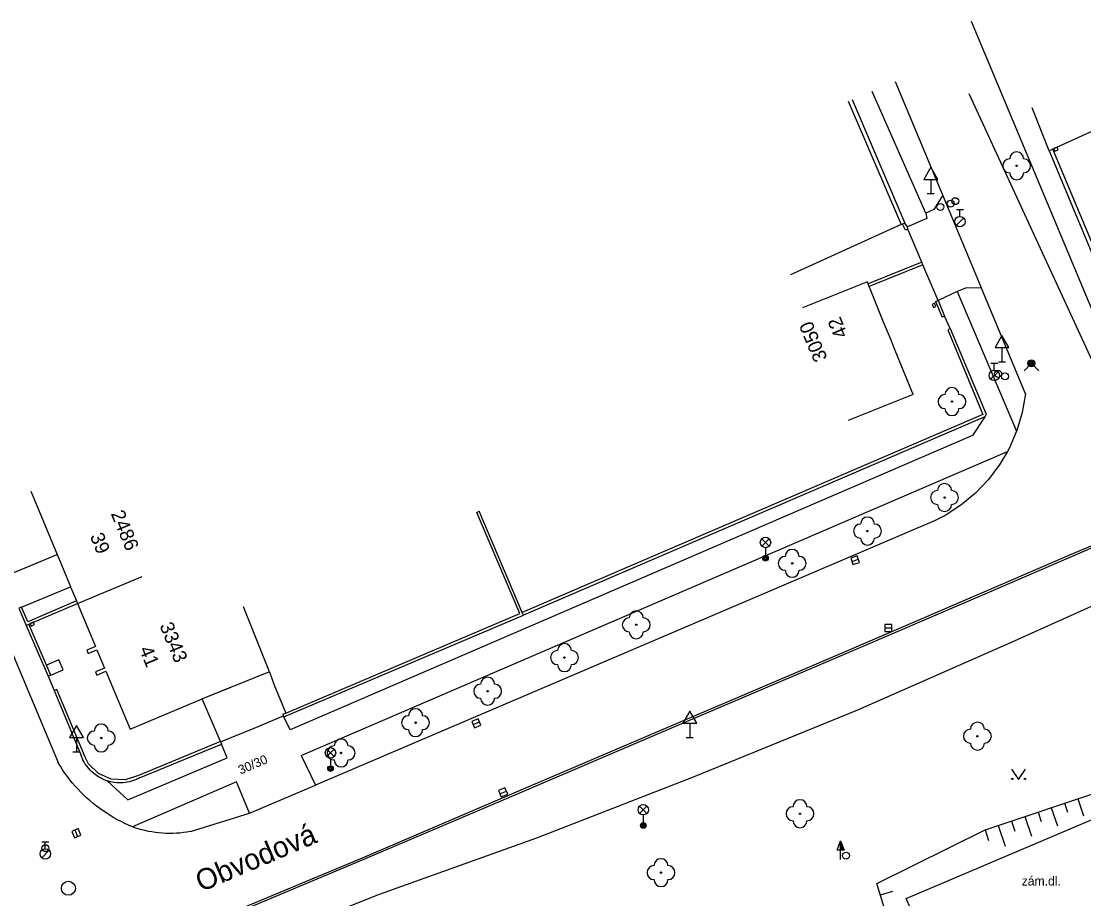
# Model space of a CAD drawing. Extents: x -539694 to -539148, y -1156467 to -1155920.
# Drawn here: x -539556.6 to -539480.5, y -1156053.8 to -1155991 of the extents above; entities that cross this region are included whole.
import ezdxf

# ---------------------------------------------------------------- set-up
doc = ezdxf.new("R2010")
doc.units = 0
for name, color, linetype in [('Vrstva 10', 7, 'Continuous'), ('Vrstva 11', 7, 'Continuous'), ('Vrstva 14', 7, 'Continuous'), ('Vrstva 15', 7, 'Continuous'), ('Vrstva 22', 7, 'Continuous'), ('Vrstva 23', 7, 'Continuous'), ('Vrstva 24', 7, 'Continuous'), ('Vrstva 27', 7, 'Continuous'), ('Vrstva 28', 7, 'Continuous'), ('Vrstva 31', 7, 'Continuous'), ('Vrstva 33', 7, 'Continuous'), ('Vrstva 34', 7, 'Continuous'), ('Vrstva 36', 7, 'Continuous'), ('Vrstva 40', 7, 'Continuous'), ('Vrstva 46', 7, 'Continuous'), ('Vrstva 47', 7, 'Continuous'), ('Vrstva 49', 7, 'Continuous'), ('Vrstva 5', 7, 'Continuous'), ('Vrstva 6', 7, 'Continuous'), ('Vrstva 7', 7, 'Continuous'), ('Vrstva 8', 7, 'Continuous')]:
    doc.layers.add(name, color=color, linetype=linetype)

msp = doc.modelspace()

# ---------------------------------------------------------------- linework, layer by layer
at = {"layer": 'Vrstva 10'}
for p, q in [((-539490.641, -1156003.461), (-539494.017, -1155995.353)), ((-539488.78, -1155996.19), (-539479.82, -1156015.6)), ((-539488.011, -1156009.777), (-539490.641, -1156003.461)), ((-539487.865, -1156010.127), (-539488.011, -1156009.777)), ((-539484.718, -1156017.686), (-539487.865, -1156010.127)), ((-539491.222, -1156026.789), (-539535.54, -1156045.71)), ((-539558.31, -1156033.77), (-539553.97, -1156044.1)), ((-539540.26, -1156047.72), (-539535.54, -1156045.71)), ((-539544.5, -1156049.04), (-539540.26, -1156047.72))]:
    msp.add_line(p, q, dxfattribs=at)
for points in [[(-539484.718, -1156017.686), (-539484.948, -1156019.021), (-539485.334, -1156020.32), (-539485.352, -1156020.371), (-539485.87, -1156021.564), (-539486.008, -1156021.831), (-539486.548, -1156022.737), (-539487.361, -1156023.821), (-539488.295, -1156024.803), (-539489.338, -1156025.667)], [(-539489.338, -1156025.667), (-539490.476, -1156026.402), (-539491.222, -1156026.789)], [(-539548.65, -1156048.7), (-539548.924, -1156048.583), (-539549.194, -1156048.459), (-539549.462, -1156048.327), (-539549.725, -1156048.189), (-539549.985, -1156048.043), (-539550.24, -1156047.891), (-539550.492, -1156047.732), (-539550.739, -1156047.565), (-539550.982, -1156047.393), (-539551.22, -1156047.214), (-539551.453, -1156047.028), (-539551.68, -1156046.837), (-539551.903, -1156046.639), (-539552.12, -1156046.436), (-539552.332, -1156046.226), (-539552.538, -1156046.011), (-539552.738, -1156045.791), (-539552.933, -1156045.565), (-539553.121, -1156045.335), (-539553.302, -1156045.099), (-539553.478, -1156044.858), (-539553.647, -1156044.613), (-539553.809, -1156044.363), (-539553.964, -1156044.109), (-539553.97, -1156044.1)], [(-539544.5, -1156049.04), (-539544.748, -1156049.082), (-539544.997, -1156049.117), (-539545.246, -1156049.143), (-539545.497, -1156049.162), (-539545.748, -1156049.172), (-539545.999, -1156049.175), (-539546.25, -1156049.169), (-539546.501, -1156049.156), (-539546.752, -1156049.135), (-539547.001, -1156049.105), (-539547.25, -1156049.068), (-539547.497, -1156049.023), (-539547.742, -1156048.97), (-539547.986, -1156048.909), (-539548.228, -1156048.84), (-539548.467, -1156048.764), (-539548.65, -1156048.7)]]:
    msp.add_lwpolyline(points, dxfattribs=at)
at = {"layer": 'Vrstva 11'}
for p, q in [((-539488.6, -1155991.01), (-539478.29, -1156015.69)), ((-539491.86, -1156004.76), (-539495.69, -1155996.05)), ((-539490.641, -1156003.461), (-539491.28, -1156004.48)), ((-539491.28, -1156004.48), (-539491.86, -1156004.76)), ((-539491.77, -1156005.13), (-539493.17, -1156005.74)), ((-539491.86, -1156004.76), (-539491.77, -1156005.13)), ((-539489.62, -1156010.36), (-539490.98, -1156011.01)), ((-539488.94, -1156010.09), (-539489.62, -1156010.36)), ((-539489.62, -1156010.36), (-539485.352, -1156020.371)), ((-539487.865, -1156010.127), (-539488.94, -1156010.09)), ((-539487.64, -1156019.33), (-539488.52, -1156020.67)), ((-539488.52, -1156020.67), (-539537.35, -1156041.76)), ((-539536.56, -1156043.59), (-539486.008, -1156021.831)), ((-539481.48, -1156029.36), (-539478.17, -1156027.94)), ((-539557.485, -1156030.633), (-539554.04, -1156029.193)), ((-539487.67, -1156031.88), (-539481.54, -1156029.23)), ((-539487.61, -1156032.01), (-539481.48, -1156029.36)), ((-539556.586, -1156032.972), (-539553.074, -1156031.505)), ((-539498.23, -1156036.41), (-539487.67, -1156031.88)), ((-539498.17, -1156036.54), (-539487.61, -1156032.01)), ((-539509.37, -1156041.16), (-539498.23, -1156036.41)), ((-539509.31, -1156041.29), (-539498.17, -1156036.54)), ((-539542.356, -1156042.585), (-539543.651, -1156039.523)), ((-539537.35, -1156041.76), (-539537.8, -1156040.82)), ((-539520.81, -1156046.06), (-539509.37, -1156041.16)), ((-539520.75, -1156046.19), (-539509.31, -1156041.29)), ((-539541.87, -1156043.75), (-539542.28, -1156042.77)), ((-539548.97, -1156046.76), (-539541.87, -1156043.75)), ((-539536.56, -1156043.59), (-539535.54, -1156045.71)), ((-539550.45, -1156045.41), (-539548.97, -1156046.76)), ((-539541.2, -1156045.47), (-539548.65, -1156048.7)), ((-539540.26, -1156047.72), (-539541.2, -1156045.47)), ((-539493.25, -1156053.83), (-539473.93, -1156045.61)), ((-539532.19, -1156050.92), (-539520.81, -1156046.06)), ((-539532.14, -1156051.05), (-539520.75, -1156046.19)), ((-539541.52, -1156054.81), (-539532.19, -1156050.92)), ((-539541.55, -1156055), (-539532.14, -1156051.05))]:
    msp.add_line(p, q, dxfattribs=at)
for points in [[(-539481.54, -1156029.23), (-539478.25, -1156027.84), (-539476.58, -1156027.09)], [(-539554.496, -1156037.84), (-539553.607, -1156037.458), (-539553.92, -1156036.73), (-539554.809, -1156037.112)], [(-539493.4, -1156059.73), (-539492.62, -1156058.93), (-539492.11, -1156057.52), (-539492.33, -1156055.98), (-539493.25, -1156053.83)]]:
    msp.add_lwpolyline(points, dxfattribs=at)
at = {"layer": 'Vrstva 14'}
for p, q in [((-539487.61, -1156048.92), (-539473.92, -1156044.33)), ((-539495.35, -1156052.75), (-539487.61, -1156048.92)), ((-539493.93, -1156057.4), (-539495.35, -1156052.75))]:
    msp.add_line(p, q, dxfattribs=at)
at = {"layer": 'Vrstva 15'}
for p, q in [((-539481.921, -1156047.013), (-539481.71, -1156047.644)), ((-539480.973, -1156046.695), (-539480.564, -1156047.914)), ((-539484.766, -1156047.966), (-539484.299, -1156049.359)), ((-539483.817, -1156047.648), (-539483.591, -1156048.323)), ((-539482.869, -1156047.331), (-539482.431, -1156048.637)), ((-539486.662, -1156048.602), (-539486.166, -1156050.081)), ((-539485.714, -1156048.284), (-539485.473, -1156049.002)), ((-539487.61, -1156048.92), (-539487.355, -1156049.681)), ((-539495.098, -1156053.574), (-539494.212, -1156053.304))]:
    msp.add_line(p, q, dxfattribs=at)
at = {"layer": 'Vrstva 22'}
for centre in [(-539485.35, -1156001.36), (-539489.98, -1156018.25), (-539490.51, -1156025.12), (-539496.03, -1156027.52), (-539501.42, -1156029.83), (-539512.58, -1156034.23), (-539517.72, -1156036.58), (-539523.22, -1156038.99), (-539528.38, -1156041.24), (-539550.88, -1156042.34), (-539488.16, -1156042.21), (-539533.71, -1156043.41), (-539500.86, -1156047.76), (-539510.81, -1156051.98)]:
    msp.add_circle(centre, 0.05, dxfattribs=at)
for centre, start, end in [((-539485.35, -1156000.86), 0, 180), ((-539485.85, -1156001.36), 90, 270), ((-539484.85, -1156001.36), 270, 90), ((-539485.35, -1156001.86), 180, 0), ((-539489.98, -1156017.75), 0, 180), ((-539490.48, -1156018.25), 90, 270), ((-539489.48, -1156018.25), 270, 90), ((-539489.98, -1156018.75), 180, 0), ((-539490.51, -1156024.62), 0, 180), ((-539491.01, -1156025.12), 90, 270), ((-539490.01, -1156025.12), 270, 90), ((-539490.51, -1156025.62), 180, 0), ((-539496.03, -1156027.02), 0, 180), ((-539496.53, -1156027.52), 90, 270), ((-539495.53, -1156027.52), 270, 90), ((-539496.03, -1156028.02), 180, 0), ((-539501.42, -1156029.33), 0, 180), ((-539501.92, -1156029.83), 90, 270), ((-539500.92, -1156029.83), 270, 90), ((-539501.42, -1156030.33), 180, 0), ((-539512.58, -1156033.73), 0, 180), ((-539513.08, -1156034.23), 90, 270), ((-539512.08, -1156034.23), 270, 90), ((-539512.58, -1156034.73), 180, 0), ((-539517.72, -1156036.08), 0, 180), ((-539518.22, -1156036.58), 90, 270), ((-539517.22, -1156036.58), 270, 90), ((-539517.72, -1156037.08), 180, 0), ((-539523.22, -1156038.49), 0, 180), ((-539523.72, -1156038.99), 90, 270), ((-539522.72, -1156038.99), 270, 90), ((-539523.22, -1156039.49), 180, 0), ((-539528.38, -1156040.74), 0, 180), ((-539528.88, -1156041.24), 90, 270), ((-539527.88, -1156041.24), 270, 90), ((-539551.38, -1156042.34), 90, 270), ((-539550.88, -1156041.84), 0, 180), ((-539550.38, -1156042.34), 270, 90), ((-539528.38, -1156041.74), 180, 0), ((-539488.66, -1156042.21), 90, 270), ((-539488.16, -1156041.71), 0, 180), ((-539487.66, -1156042.21), 270, 90), ((-539533.71, -1156042.91), 0, 180), ((-539550.88, -1156042.84), 180, 0), ((-539534.21, -1156043.41), 90, 270), ((-539533.21, -1156043.41), 270, 90), ((-539488.16, -1156042.71), 180, 0), ((-539533.71, -1156043.91), 180, 0), ((-539500.86, -1156047.26), 0, 180), ((-539501.36, -1156047.76), 90, 270), ((-539500.36, -1156047.76), 270, 90), ((-539500.86, -1156048.26), 180, 0), ((-539510.81, -1156051.48), 0, 180), ((-539511.31, -1156051.98), 90, 270), ((-539510.31, -1156051.98), 270, 90), ((-539510.81, -1156052.48), 180, 0)]:
    msp.add_arc(centre, 0.5, start, end, dxfattribs=at)
at = {"layer": 'Vrstva 23'}
for p, q in [((-539485.73, -1156035.47), (-539476.98, -1156031.53)), ((-539496.72, -1156040.33), (-539485.73, -1156035.47)), ((-539508.48, -1156045.13), (-539496.72, -1156040.33)), ((-539519.7, -1156049.48), (-539508.48, -1156045.13)), ((-539530.96, -1156053.51), (-539519.7, -1156049.48)), ((-539541.12, -1156057.56), (-539530.96, -1156053.51))]:
    msp.add_line(p, q, dxfattribs=at)
at = {"layer": 'Vrstva 24'}
for p, q in [((-539482.457, -1156000.035), (-539482.689, -1156000.128)), ((-539482.383, -1156000.221), (-539482.457, -1156000.035)), ((-539482.689, -1156000.128), (-539482.615, -1156000.314)), ((-539482.615, -1156000.314), (-539482.383, -1156000.221)), ((-539491.223, -1156011.21), (-539491.408, -1156011.285)), ((-539491.408, -1156011.285), (-539491.314, -1156011.517)), ((-539491.314, -1156011.517), (-539491.129, -1156011.442)), ((-539491.129, -1156011.442), (-539491.223, -1156011.21)), ((-539555.749, -1156034.038), (-539555.979, -1156034.135)), ((-539555.979, -1156034.135), (-539555.901, -1156034.32)), ((-539555.901, -1156034.32), (-539555.671, -1156034.222)), ((-539555.671, -1156034.222), (-539555.749, -1156034.038))]:
    msp.add_line(p, q, dxfattribs=at)
at = {"layer": 'Vrstva 27'}
for p, q in [((-539497.148, -1156029.689), (-539496.676, -1156029.525)), ((-539494.79, -1156034.46), (-539494.29, -1156034.46)), ((-539524.259, -1156041.381), (-539523.799, -1156041.187)), ((-539522.342, -1156046.328), (-539521.882, -1156046.134)), ((-539552.764, -1156048.925), (-539552.57, -1156049.385))]:
    msp.add_line(p, q, dxfattribs=at)
for points in [[(-539497.067, -1156029.925), (-539496.594, -1156029.762), (-539496.757, -1156029.289), (-539497.23, -1156029.452)], [(-539494.79, -1156034.71), (-539494.29, -1156034.71), (-539494.29, -1156034.21), (-539494.79, -1156034.21)], [(-539524.162, -1156041.611), (-539523.702, -1156041.417), (-539523.896, -1156040.957), (-539524.356, -1156041.151)], [(-539522.245, -1156046.558), (-539521.785, -1156046.364), (-539521.979, -1156045.904), (-539522.439, -1156046.098)], [(-539552.995, -1156049.022), (-539552.8, -1156049.483), (-539552.339, -1156049.288), (-539552.534, -1156048.827)]]:
    msp.add_lwpolyline(points, close=True, dxfattribs=at)
msp.add_circle((-539553.235, -1156053.1), 0.5, dxfattribs=at)
at = {"layer": 'Vrstva 28'}
for p, q in [((-539489.664, -1156004.482), (-539489.164, -1156004.482)), ((-539489.414, -1156004.982), (-539489.414, -1156004.482)), ((-539489.672, -1156005.629), (-539489.142, -1156005.099)), ((-539487.204, -1156015.498), (-539486.704, -1156015.498)), ((-539486.954, -1156015.998), (-539486.954, -1156015.498)), ((-539487.212, -1156016.645), (-539486.682, -1156016.115)), ((-539555.136, -1156049.764), (-539554.636, -1156049.764)), ((-539554.886, -1156050.264), (-539554.886, -1156049.764)), ((-539498.2, -1156050.378), (-539497.95, -1156049.704)), ((-539555.144, -1156050.911), (-539554.614, -1156050.381)), ((-539497.95, -1156050.378), (-539498.2, -1156050.378)), ((-539497.95, -1156051.03), (-539497.95, -1156050.38))]:
    msp.add_line(p, q, dxfattribs=at)
for points in [[(-539497.7, -1156050.38), (-539497.95, -1156050.38), (-539497.95, -1156049.704), (-539497.7, -1156050.38)], [(-539497.756, -1156050.339), (-539497.911, -1156050.339), (-539497.909, -1156049.927)], [(-539497.815, -1156050.3), (-539497.871, -1156050.3), (-539497.871, -1156050.15)]]:
    msp.add_lwpolyline(points, close=True, dxfattribs=at)
for centre, radius in [((-539490.077, -1156004.068), 0.25), ((-539489.748, -1156003.895), 0.25), ((-539490.81, -1156004.31), 0.25), ((-539489.414, -1156005.357), 0.375), ((-539486.954, -1156016.373), 0.375), ((-539486.676, -1156016.261), 0.25), ((-539486.18, -1156016.44), 0.25), ((-539554.886, -1156050.639), 0.375), ((-539554.879, -1156050.227), 0.25), ((-539497.56, -1156050.76), 0.25)]:
    msp.add_circle(centre, radius, dxfattribs=at)
at = {"layer": 'Vrstva 31'}
msp.add_lwpolyline([(-539484.824, -1156016.037), (-539484.294, -1156015.507), (-539483.764, -1156016.037)], dxfattribs=at)
for radius in [0.25, 0.18, 0.11]:
    msp.add_circle((-539484.294, -1156015.507), radius, dxfattribs=at)
at = {"layer": 'Vrstva 33'}
for p, q in [((-539503.595, -1156028.6), (-539503.065, -1156028.07)), ((-539503.595, -1156028.07), (-539503.065, -1156028.6)), ((-539503.33, -1156028.71), (-539503.33, -1156029.46)), ((-539534.735, -1156043.67), (-539534.205, -1156043.14)), ((-539534.735, -1156043.14), (-539534.205, -1156043.67)), ((-539534.47, -1156043.78), (-539534.47, -1156044.53)), ((-539512.344, -1156047.741), (-539511.816, -1156047.211)), ((-539512.344, -1156047.211), (-539511.816, -1156047.741)), ((-539512.08, -1156047.85), (-539512.08, -1156048.6))]:
    msp.add_line(p, q, dxfattribs=at)
for centre, radius in [((-539503.33, -1156028.335), 0.375), ((-539503.33, -1156029.46), 0.2), ((-539503.33, -1156029.46), 0.145), ((-539503.33, -1156029.46), 0.0876), ((-539534.47, -1156043.405), 0.375), ((-539534.47, -1156044.53), 0.2), ((-539534.47, -1156044.53), 0.145), ((-539534.47, -1156044.53), 0.0876), ((-539512.08, -1156047.476), 0.375), ((-539512.08, -1156048.601), 0.2), ((-539512.08, -1156048.601), 0.145), ((-539512.08, -1156048.601), 0.0876)]:
    msp.add_circle(centre, radius, dxfattribs=at)
at = {"layer": 'Vrstva 34'}
for p, q in [((-539491.5, -1156002.332), (-539491.5, -1156003.35)), ((-539491.75, -1156003.35), (-539491.25, -1156003.35)), ((-539486.4, -1156014.382), (-539486.4, -1156015.4)), ((-539486.65, -1156015.4), (-539486.15, -1156015.4)), ((-539508.75, -1156041.284), (-539508.75, -1156042.3)), ((-539552.66, -1156042.312), (-539552.66, -1156043.33)), ((-539509, -1156042.3), (-539508.5, -1156042.3)), ((-539552.91, -1156043.33), (-539552.41, -1156043.33))]:
    msp.add_line(p, q, dxfattribs=at)
for points in [[(-539492, -1156002.332), (-539491, -1156002.332), (-539491.5, -1156001.466)], [(-539486.9, -1156014.382), (-539485.9, -1156014.382), (-539486.4, -1156013.516)], [(-539509.25, -1156041.284), (-539508.25, -1156041.284), (-539508.75, -1156040.416)], [(-539553.16, -1156042.312), (-539552.16, -1156042.312), (-539552.66, -1156041.446)]]:
    msp.add_lwpolyline(points, close=True, dxfattribs=at)
at = {"layer": 'Vrstva 36'}
msp.add_lwpolyline([(-539485.71, -1156044.57), (-539485.21, -1156045.32), (-539484.71, -1156044.57)], dxfattribs=at)
for centre in [(-539485.66, -1156045.27), (-539484.761, -1156045.27)]:
    msp.add_circle(centre, 0.05, dxfattribs=at)
at = {"layer": 'Vrstva 5'}
for p, q in [((-539496.036, -1156009.667), (-539500.677, -1156011.528)), ((-539495.979, -1156009.809), (-539496.036, -1156009.667)), ((-539495.904, -1156009.994), (-539495.979, -1156009.809)), ((-539495.79, -1156010.28), (-539495.904, -1156009.994)), ((-539494.88, -1156012.55), (-539495.79, -1156010.28)), ((-539494.39, -1156013.72), (-539494.88, -1156012.55)), ((-539494.04, -1156014.6), (-539494.39, -1156013.72)), ((-539492.77, -1156017.74), (-539494.04, -1156014.6)), ((-539492.77, -1156017.74), (-539497.411, -1156019.601)), ((-539555.93, -1156024.673), (-539554.04, -1156029.193)), ((-539554.04, -1156029.193), (-539554.024, -1156029.237)), ((-539554.024, -1156029.237), (-539553.098, -1156031.451)), ((-539552.57, -1156032.71), (-539547.957, -1156030.781)), ((-539553.098, -1156031.451), (-539553.074, -1156031.505)), ((-539553.074, -1156031.505), (-539552.648, -1156032.526)), ((-539552.648, -1156032.526), (-539552.57, -1156032.71)), ((-539552.57, -1156032.71), (-539551.284, -1156035.795)), ((-539538.84, -1156037.59), (-539540.704, -1156032.95)), ((-539551.284, -1156035.795), (-539551.92, -1156036.06)), ((-539551.92, -1156036.06), (-539551.823, -1156036.29)), ((-539551.823, -1156036.29), (-539551.187, -1156036.025)), ((-539551.187, -1156036.025), (-539550.644, -1156037.332)), ((-539550.644, -1156037.332), (-539551.286, -1156037.599)), ((-539551.286, -1156037.599), (-539551.19, -1156037.83)), ((-539551.19, -1156037.83), (-539550.548, -1156037.563)), ((-539550.548, -1156037.563), (-539548.82, -1156041.71)), ((-539541.18, -1156038.53), (-539539.121, -1156037.701)), ((-539539.121, -1156037.701), (-539538.84, -1156037.59)), ((-539543.62, -1156039.51), (-539541.59, -1156038.69)), ((-539541.59, -1156038.69), (-539541.561, -1156038.681)), ((-539541.561, -1156038.681), (-539541.18, -1156038.53)), ((-539548.82, -1156041.71), (-539543.651, -1156039.523)), ((-539543.651, -1156039.523), (-539543.62, -1156039.51))]:
    msp.add_line(p, q, dxfattribs=at)
at = {"layer": 'Vrstva 6'}
for p, q in [((-539494.88, -1156012.55), (-539495.79, -1156010.28)), ((-539494.04, -1156014.6), (-539494.39, -1156013.72)), ((-539554.024, -1156029.237), (-539553.098, -1156031.451)), ((-539551.187, -1156036.025), (-539550.644, -1156037.332)), ((-539541.18, -1156038.53), (-539539.121, -1156037.701)), ((-539543.62, -1156039.51), (-539541.561, -1156038.681))]:
    msp.add_line(p, q, dxfattribs=at)
at = {"layer": 'Vrstva 7'}
for p, q in [((-539497.405, -1155996.737), (-539493.625, -1156005.577)), ((-539497.13, -1155996.62), (-539493.35, -1156005.46)), ((-539483.03, -1156000.29), (-539484.25, -1155997.21)), ((-539483.03, -1156000.29), (-539476.99, -1156014.78)), ((-539476.829, -1156014.386), (-539482.757, -1156000.166)), ((-539493.319, -1156005.977), (-539493.529, -1156005.547)), ((-539493.14, -1156005.89), (-539493.319, -1156005.977)), ((-539492.14, -1156008.27), (-539495.979, -1156009.809)), ((-539492.065, -1156008.455), (-539492.14, -1156008.27)), ((-539492.065, -1156008.455), (-539495.904, -1156009.994)), ((-539491.164, -1156011.087), (-539490.98, -1156011.01)), ((-539491.164, -1156011.087), (-539490.694, -1156012.207)), ((-539490.98, -1156011.01), (-539490.51, -1156012.13)), ((-539490.51, -1156012.13), (-539490.694, -1156012.207)), ((-539490.1, -1156013.02), (-539490.284, -1156013.097)), ((-539490.284, -1156013.097), (-539487.78, -1156019.172)), ((-539490.1, -1156013.02), (-539487.53, -1156019.14)), ((-539487.78, -1156019.172), (-539520.739, -1156033.356)), ((-539487.64, -1156019.33), (-539520.66, -1156033.54)), ((-539487.53, -1156019.14), (-539487.64, -1156019.33)), ((-539524.003, -1156026.18), (-539523.819, -1156026.102)), ((-539520.922, -1156033.434), (-539524.003, -1156026.18)), ((-539520.739, -1156033.356), (-539523.819, -1156026.102)), ((-539556.586, -1156032.972), (-539556.77, -1156033.05)), ((-539537.8, -1156040.82), (-539520.66, -1156033.54)), ((-539537.672, -1156040.55), (-539520.922, -1156033.434)), ((-539520.66, -1156033.54), (-539520.739, -1156033.356)), ((-539556.25, -1156034.27), (-539554.68, -1156037.92)), ((-539554.496, -1156037.84), (-539554.68, -1156037.92)), ((-539554.065, -1156038.853), (-539554.25, -1156038.93)), ((-539552.031, -1156043.717), (-539554.065, -1156038.853)), ((-539538.53, -1156038.48), (-539537.672, -1156040.55)), ((-539554.25, -1156038.93), (-539552.32, -1156043.59)), ((-539537.876, -1156040.635), (-539537.672, -1156040.55)), ((-539542.356, -1156042.585), (-539548.216, -1156045.015)), ((-539548.14, -1156045.2), (-539542.28, -1156042.77))]:
    msp.add_line(p, q, dxfattribs=at)
for points in [[(-539475.812, -1155996.787), (-539475.729, -1155996.969), (-539482.757, -1156000.166), (-539483.03, -1156000.29)], [(-539493.35, -1156005.46), (-539493.529, -1156005.547), (-539493.625, -1156005.577), (-539501.543, -1156009.163)], [(-539493.14, -1156005.89), (-539493.17, -1156005.74), (-539493.35, -1156005.46)], [(-539556.77, -1156033.05), (-539556.25, -1156034.27), (-539556.066, -1156034.19), (-539552.57, -1156032.71)], [(-539552.648, -1156032.526), (-539556.144, -1156034.008), (-539556.586, -1156032.972)], [(-539554.496, -1156037.84), (-539554.809, -1156037.112), (-539556.066, -1156034.19)], [(-539537.876, -1156040.635), (-539537.824, -1156040.761), (-539537.8, -1156040.82)], [(-539542.356, -1156042.585), (-539542.343, -1156042.617), (-539542.28, -1156042.77)], [(-539548.14, -1156045.2), (-539548.277, -1156045.269), (-539548.417, -1156045.332), (-539548.561, -1156045.386), (-539548.707, -1156045.434), (-539548.855, -1156045.473), (-539549.006, -1156045.505), (-539549.157, -1156045.529), (-539549.31, -1156045.545), (-539549.464, -1156045.553), (-539549.617, -1156045.553), (-539549.771, -1156045.545), (-539549.923, -1156045.529), (-539550.075, -1156045.505), (-539550.225, -1156045.473), (-539550.374, -1156045.434), (-539550.45, -1156045.41), (-539550.52, -1156045.386), (-539550.663, -1156045.332), (-539550.804, -1156045.269), (-539550.941, -1156045.2), (-539551.074, -1156045.124), (-539551.203, -1156045.04), (-539551.328, -1156044.951), (-539551.447, -1156044.854), (-539551.562, -1156044.752), (-539551.671, -1156044.644), (-539551.774, -1156044.53), (-539551.871, -1156044.411), (-539551.962, -1156044.287), (-539552.047, -1156044.159), (-539552.124, -1156044.027), (-539552.195, -1156043.89), (-539552.258, -1156043.75), (-539552.314, -1156043.607), (-539552.32, -1156043.59)], [(-539548.216, -1156045.015), (-539549.177, -1156045.33), (-539550.167, -1156045.281), (-539551.075, -1156044.886), (-539551.784, -1156044.193), (-539552.031, -1156043.717)]]:
    msp.add_lwpolyline(points, dxfattribs=at)
at = {"layer": 'Vrstva 8'}
for p, q in [((-539492.14, -1156008.27), (-539493.14, -1156005.89)), ((-539490.98, -1156011.01), (-539492.065, -1156008.455)), ((-539490.1, -1156013.02), (-539490.51, -1156012.13)), ((-539554.68, -1156037.92), (-539554.25, -1156038.93)), ((-539538.84, -1156037.59), (-539538.53, -1156038.48)), ((-539539.94, -1156041.63), (-539537.824, -1156040.761)), ((-539542.343, -1156042.617), (-539539.94, -1156041.63))]:
    msp.add_line(p, q, dxfattribs=at)

# ---------------------------------------------------------------- texts
at = {"layer": 'Vrstva 40'}
msp.add_text('30/30', height=0.65, rotation=23.20593, dxfattribs=at).set_placement((-539540.907, -1156044.962))
msp.add_text('zám.dl.', height=0.65, dxfattribs=at).set_placement((-539484.987, -1156052.901))
at = {"layer": 'Vrstva 46'}
for s, rotation, p in [('42', 112.77235, (-539497.415, -1156013.464)), ('39', 292.42866, (-539551.708, -1156027.882)), ('41', 292.42866, (-539548.187, -1156035.99))]:
    msp.add_text(s, height=1, rotation=rotation, dxfattribs=at).set_placement(p)
at = {"layer": 'Vrstva 47'}
for s, rotation, p in [('3050', 112.77235, (-539498.879, -1156015.145)), ('2486', 292.42866, (-539550.211, -1156026.268)), ('3343', 292.42866, (-539546.725, -1156034.288))]:
    msp.add_text(s, height=1, rotation=rotation, dxfattribs=at).set_placement(p)
at = {"layer": 'Vrstva 49'}
msp.add_text('Obvodová', height=1.5, rotation=23.16445, dxfattribs=at).set_placement((-539543.734, -1156053.384))

doc.saveas('drawing.dxf')
